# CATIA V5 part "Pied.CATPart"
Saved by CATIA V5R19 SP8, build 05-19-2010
Part number: Profilé Maker 100089.1
Bounding box of the stored display mesh (mm): x 0 to 144.919, y -5 to 5, z -5 to 5
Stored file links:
  D:\Documents\1_Travail\1 - ac-limoges.fr\ac-limoges.fr\Emmanuel Maynard - STI2D_Turgot\1 - IT-I2D\Activités_IT_Première\IT_3_Abris_bus\Maquettes numériques\Abribus_eleve\Pied.CATPart
  C:\Program Files\Dassault Systemes\B19\win_b64\reffiles\standard\MetricThickPitch.txt
  D:\Documents\1_Travail\2- 2I2D\6 -  Ressources ITEC\Ressources Techniques\0-Maquettes numériques_Composants\Catalogue_Makeblock\Catalog_Makeblock\12_MakerBeam\TableMakerbeam.xls
  D:\Documents\1_Travail\2- 2I2D\6 -  Ressources ITEC\Ressources Techniques\0-Maquettes numériques_Composants\Catalogue_Makeblock\Catalog_Makeblock\12_MakerBeam\TableMakerbeam.txt
  D:\Documents\1_Travail\1 - ac-limoges.fr\ac-limoges.fr\Emmanuel Maynard - STI2D_Turgot\1 - IT-I2D\Activités_IT_Première\IT_3_Abris_bus\Maquettes numériques\Abribus\0-Abribus.CATProduct
  D:\Documents\1_Travail\1 - ac-limoges.fr\ac-limoges.fr\Emmanuel Maynard - STI2D_Turgot\1 - IT-I2D\Activités_IT_Première\IT_3_Abris_bus\Maquettes numériques\Abribus\Cube d'angle.CATPart
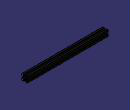
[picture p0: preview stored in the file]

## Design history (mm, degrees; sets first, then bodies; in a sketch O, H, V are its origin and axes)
AxisSystem1: origin (0, 0, 0), X (1, 0, 0), Y (0, 1, 0), Z (0, 0, 1)
Set1
  DatumSurface1
Body1 (main body)
  Sketch1 on YZ plane of AxisSystem1, origin (0, 0, 0), H (0, 1, 0), V (0, 0, 1)
    line L1 (-5, 5) -> (-1.5, 5)
    point P1 (5, 5)
    point P2 (-5, 5)
    arc A1 centre (0, 0) radius 1.2 from (0, 1.2) to (-0.8485, 0.8485) ccw
    line L2 (-0.8485, 0.8485) -> (-5, 5)
    line L3 (0, 1.2) -> (0, 2)
    reference intersected line E1 through (0, 0) direction (-1, 0) from XY plane of AxisSystem1
    reference intersected line E2 through (0, 0) direction (0, 1) from ZX plane of AxisSystem1
    line L4 (-1.5, 5) -> (-1.5, 4)
    line L5 (-1.5, 4) -> (-3.2929, 4)
    line L6 (-3.2929, 4) -> (-1, 2)
    line L7 (-1, 2) -> (0, 2)
    reference projected line E3 through (0, 0) direction (0, 1) from edge [ZX plane of AxisSystem1 | YZ plane of AxisSystem1]
    radius A1 = 1.2
    distance L1 E1 = 5
    distance P2 E3 = 5
    distance L4 P2 = 3.5
    length L7 = 1
    distance L5 L1 = 1
    distance L7 L1 = 3
    angle L6 L3 = 48.903
    horizontal: L1 H, L5 H, L7 H
    vertical: L3 V, L4 V
    coincidence: L3 E2, L2 O
  Pad1: profile Sketch1, direction (1, 0, 0), up to face of DatumSurface1
  Fillet1: radius 0.2, on edge [face of Pad1 from Sketch1.L5 | face of Pad1 from Sketch1.L6]; edge [face of Pad1 from Sketch1.L6 | face of Pad1 from Sketch1.L7]; edge [face of Pad1 from Sketch1.L1 | face of Pad1 from Sketch1.L4]; edge [face of Pad1 from Sketch1.L4 | face of Pad1 from Sketch1.L5]
  Mirror1: of the body so far, about face of Pad1 from Sketch1.L2
  Fillet2: radius 0.2, on edge [face of Mirror1 | face of Pad1 from Sketch1.L1]
  Mirror2: of the body so far, about face of Mirror1
  Mirror3: of the body so far, about face of Pad1 from Sketch1.L3
  Sketch2 on face of Pad1, origin (144.9193, 0.9666, 1.0824), H (0, 1, 0), V (0, 0, 1)
    point P1 (-0.9666, -1.0824)
    projected point E1 (-0.9666, -1.0824) from axis of face of Mirror3
    coincidence: E1 P1
  Hole1: placed by Sketch2, at (144.9193, 0, 0) direction (-1, 0, 0), diameter 2.459, depth 10, threaded "M3", thread diameter 3, thread depth 8, pitch 0.5
  Sketch3 on face of Pad1, origin (0, -1.3866, 1.2369), H (0, 1, 0), V (0, 0, -1)
    point P1 (1.3866, 1.2369)
    reference projected point E1 (1.3866, 1.2369) from axis of face of Pad1
    coincidence: P1 E1
  Hole2: placed by Sketch3, at (0, 0, 0) direction (1, 0, 0), diameter 2.459, depth 10, threaded "M3", thread diameter 3, thread depth 8, pitch 0.5
Current feature: Mirror3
